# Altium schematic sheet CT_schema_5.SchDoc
size 383 x 299 mm
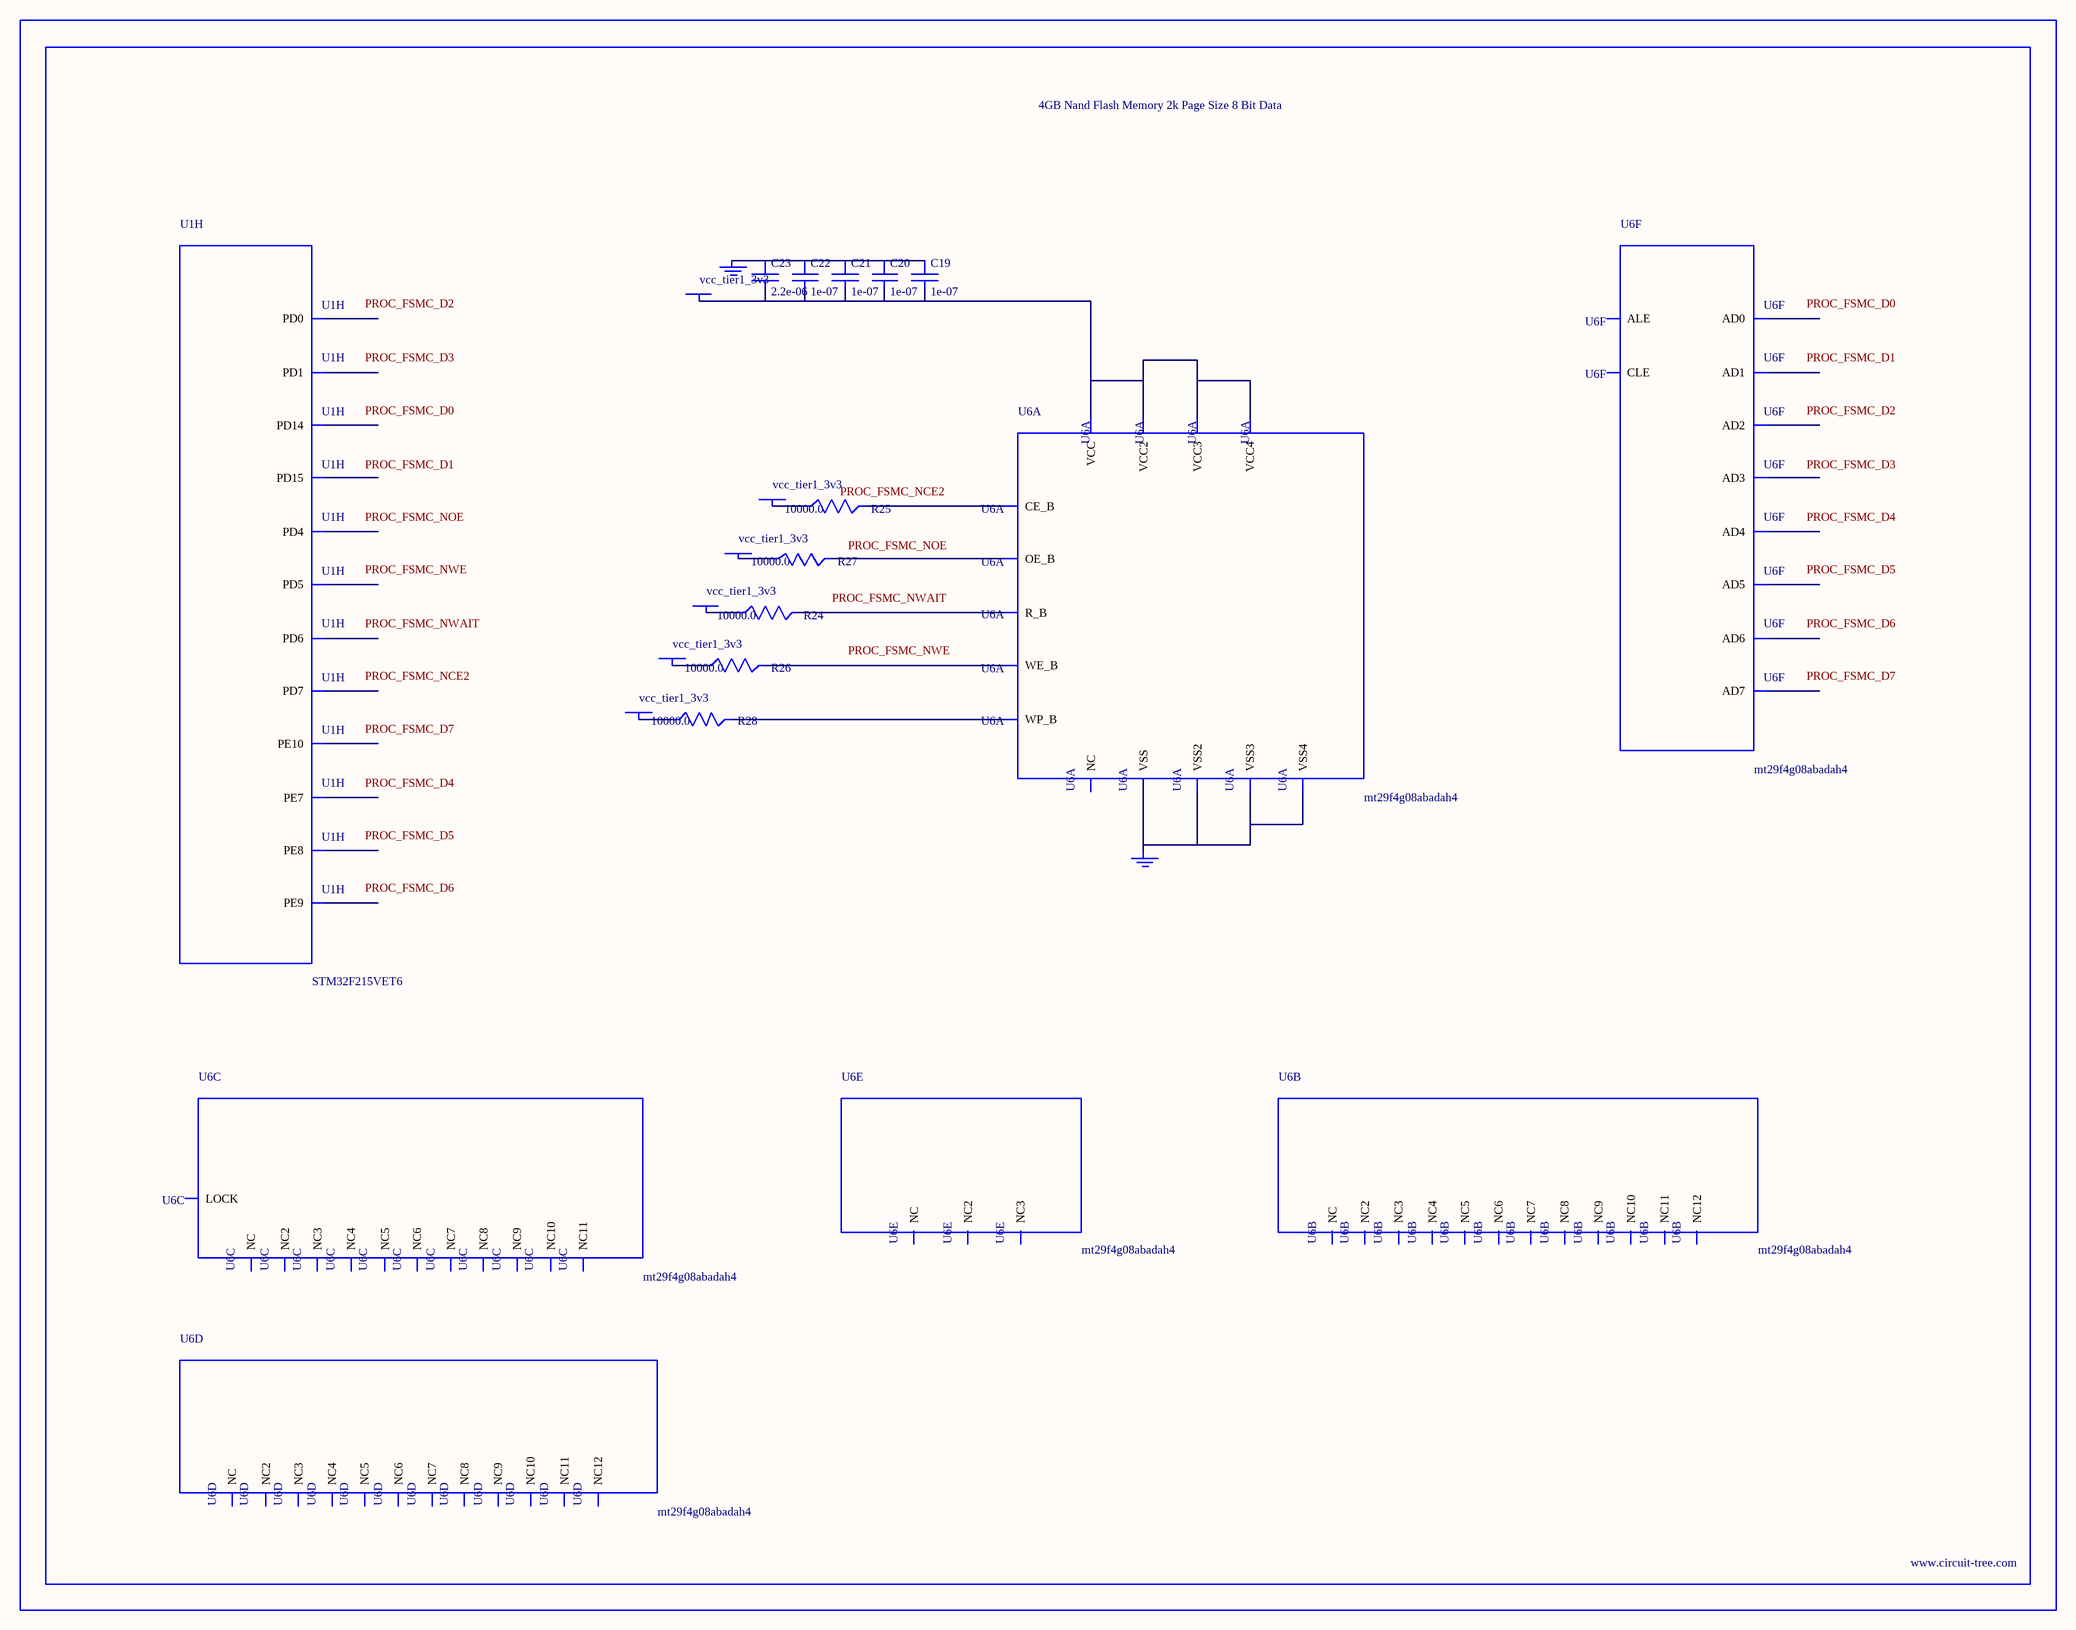
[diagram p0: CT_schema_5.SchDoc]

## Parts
BORDER4  (no value)
C19  1e-07  [C0402]
C20  1e-07  [C0402]
C21  1e-07  [C0402]
C22  1e-07  [C0402]
C23  2.2e-06  [C0603]
GND_INSTANCE_4_0  (no value)
GND_INSTANCE_4_1  (no value)
POWER_INSTANCE_4_0  vcc_tier1_3v3
POWER_INSTANCE_4_1  vcc_tier1_3v3
POWER_INSTANCE_4_2  vcc_tier1_3v3
POWER_INSTANCE_4_3  vcc_tier1_3v3
POWER_INSTANCE_4_4  vcc_tier1_3v3
POWER_INSTANCE_4_5  vcc_tier1_3v3
R24  10000.0  [R0603]
R25  10000.0  [R0603]
R26  10000.0  [R0603]
R27  10000.0  [R0603]
R28  10000.0  [R0603]
U1  STM32F215VET6  [LQFP100]  (part H of 9)
U6  mt29f4g08abadah4  [VFBGA-63]  (parts A,B,C,D,E,F of 6)

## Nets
NetC19_1: C19.1 C20.1 C21.1 C22.1 C23.1 GND_INSTANCE_4_0.0(GND)
NetC19_2: C19.2 C20.2 C21.2 C22.2 C23.2 POWER_INSTANCE_4_0.0(PWR) U6.D3(VCC) U6.G4(VCC2) U6.H8(VCC3) U6.J6(VCC4)
NetGND_INSTANCE_4_1_0: GND_INSTANCE_4_1.0(GND) U6.C5(VSS) U6.F7(VSS2) U6.K3(VSS3) U6.K8(VSS4)
NetPOWER_INSTANCE_4_1_0: POWER_INSTANCE_4_1.0(PWR) R24.1
NetPOWER_INSTANCE_4_2_0: POWER_INSTANCE_4_2.0(PWR) R25.1
NetPOWER_INSTANCE_4_3_0: POWER_INSTANCE_4_3.0(PWR) R26.1
NetPOWER_INSTANCE_4_4_0: POWER_INSTANCE_4_4.0(PWR) R27.1
NetPOWER_INSTANCE_4_5_0: POWER_INSTANCE_4_5.0(PWR) R28.1
NetR24_2: R24.2 U6.C8(R_B)
NetR25_2: R25.2 U6.C6(CE_B)
NetR26_2: R26.2 U6.C7(WE_B)
NetR27_2: R27.2 U6.D4(OE_B)
NetR28_2: R28.2 U6.C3(WP_B)

Not connected (* = marked no-connect by the designer): U1 38(PE7) 39(PE8) 40(PE9) 41(PE10) 61(PD14) 62(PD15) 81(PD0) 82(PD1) 85(PD4) 86(PD5) 87(PD6) 88(PD7); U6 A1(NC) A2(NC3) A9(NC4) A10(NC2) B1(NC5) B9(NC7) B10(NC6) C4(ALE) D5(CLE) D6(NC8) D7(NC9) D8(NC10) E3(NC11) E4(NC12) E5(NC) E6(NC2) E7(NC3) E8(NC4) F3(NC5) F4(NC6) F5(NC7) F6(NC8) F8(NC9) G3(NC) G5(LOCK) G6(NC10) G7(NC11) G8(NC) H3(NC2) H4(AD0) H5(NC3) H6(NC4) H7(NC5) J3(NC6) J4(AD1) J5(NC7) J7(AD5) J8(AD7) K4(AD2) K5(AD3) K6(AD4) K7(AD6) L1(NC8) L2(NC10) L9(NC11) L10(NC9) M1(NC12) M2(NC2) M9(NC3) M10(NC)

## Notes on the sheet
- Labels drawn without touching a wire or pin: PROC_FSMC_D0, PROC_FSMC_D1, PROC_FSMC_D2, PROC_FSMC_D3, PROC_FSMC_D4, PROC_FSMC_D5, PROC_FSMC_D6, PROC_FSMC_D7, PROC_FSMC_NCE2, PROC_FSMC_NOE, PROC_FSMC_NWAIT, PROC_FSMC_NWE

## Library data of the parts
BORDER4 = BORDER_PAGE4
C19-C22 = C0402C104K3RACTU
C23 = C0603C225K8RACTU
GND_INSTANCE_4_0 GND_INSTANCE_4_1 = GND
POWER_INSTANCE_4_0-POWER_INSTANCE_4_5 = PWR
R24-R28 = RC0603JR-0710KL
